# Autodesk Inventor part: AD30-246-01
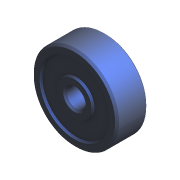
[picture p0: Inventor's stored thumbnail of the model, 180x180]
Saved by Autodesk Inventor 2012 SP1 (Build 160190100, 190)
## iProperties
Shininess: 0.0
Length Units: 11269
Angle Units: 11279
Time Units: 11290
Mass Units: 11283
Length Display Precision: 3
Angle Display Precision: 2
Compacted: True
Created: 2000-07
Part Number: AD30-246-01
Description: DETENT ROLLER
Document SubType Name: Modeling
Designer: Ron
Density: 1 g/cm^3
Material: Default
Density: 0.0
Volumn: 0.0
Area: 0.0
PropertySet Name: Model Information
Control State: 0
Master: False
Checked Out: False
Author: Ron
Revision Number: A
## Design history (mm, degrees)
node "Extrusion1" dims "d2" = 8, "d3" = 0
  sketch "Sketch1"
    geometry: C1 r 11 at (0, 0); C2 r 2.4 at (0, 0); 1 further point
    constraints: 2 centre point, 2 coincident
    dimensions: "dia" = 22 diameter of C1; "d1" = 4.8 diameter of C2
sketch "Sketch2"
  geometry: C1 r 2.4 at (0, 0) reference; C2 r 11 at (0, 0) reference; C3 r 4.4 at (0, 0); C4 r 9 at (0, 0)
  constraints: 2 centre point
  dimensions: "d7" = 2 radial gap between concentric circles of C2 C4; "d8" = 2 radial gap between concentric circles of C3 C1
extrude "Extrusion2" cut sketch "Sketch2" distance "d9" = 0.5; taper "d10" = -30 deg
mirror "Mirror1"
chamfer "Chamfer2" distance "d11" = 0.5; stored, may be unused: second distance "d12" = 2, angle "d13" = 45 deg
sketch "Sketch3"
  geometry: L1 (11, 3.5)-(11, -3.5) reference; L2 (11, 0.75)-(10.25, 0); L3 (10.25, 0)-(11, -0.75); L4 (0, 0)-(0, 5.471)
  constraints: 6 end point, 2 perpendicular, 2 point on line, 1 horizontal alignment, 1 parallel
  dimensions: "d14" = 1.5 distance of L2.start L3.end
revolve "Groove" sketch "Sketch3" stored, may be unused: angle "d15" = 90 deg
body "Solid1"
